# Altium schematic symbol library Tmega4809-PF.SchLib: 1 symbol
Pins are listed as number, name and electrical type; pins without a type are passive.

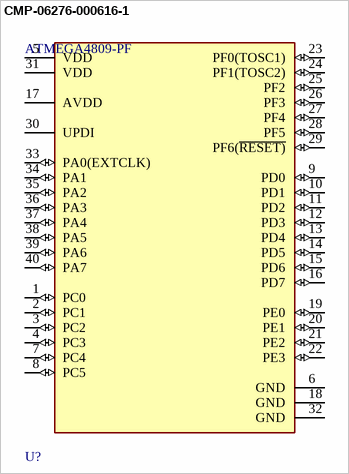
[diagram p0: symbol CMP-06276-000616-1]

## CMP-06276-000616-1
designator U?, comment ATMEGA4809-PF
IC MCU 8BIT 48KB FLASH 40DIP
footprint FP-C04-016-MFG
pins: 1 PC0 (io), 2 PC1 (io), 3 PC2 (io), 4 PC3 (io), 5 VDD (power), 6 GND (power), 7 PC4 (io), 8 PC5 (io), 9 PD0 (io), 10 PD1 (io), 11 PD2 (io), 12 PD3 (io), 13 PD4 (io), 14 PD5 (io), 15 PD6 (io), 16 PD7 (io), 17 AVDD (power), 18 GND (power), 19 PE0 (io), 20 PE1 (io), 21 PE2 (io), 22 PE3 (io), 23 PF0(TOSC1) (io), 24 PF1(TOSC2) (io), 25 PF2 (io), 26 PF3 (io), 27 PF4 (io), 28 PF5 (io), 29 PF6(~{RESET)} (io), 30 UPDI, 31 VDD (power), 32 GND (power), 33 PA0(EXTCLK) (io), 34 PA1 (io), 35 PA2 (io), 36 PA3 (io), 37 PA4 (io), 38 PA5 (io), 39 PA6 (io), 40 PA7 (io)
